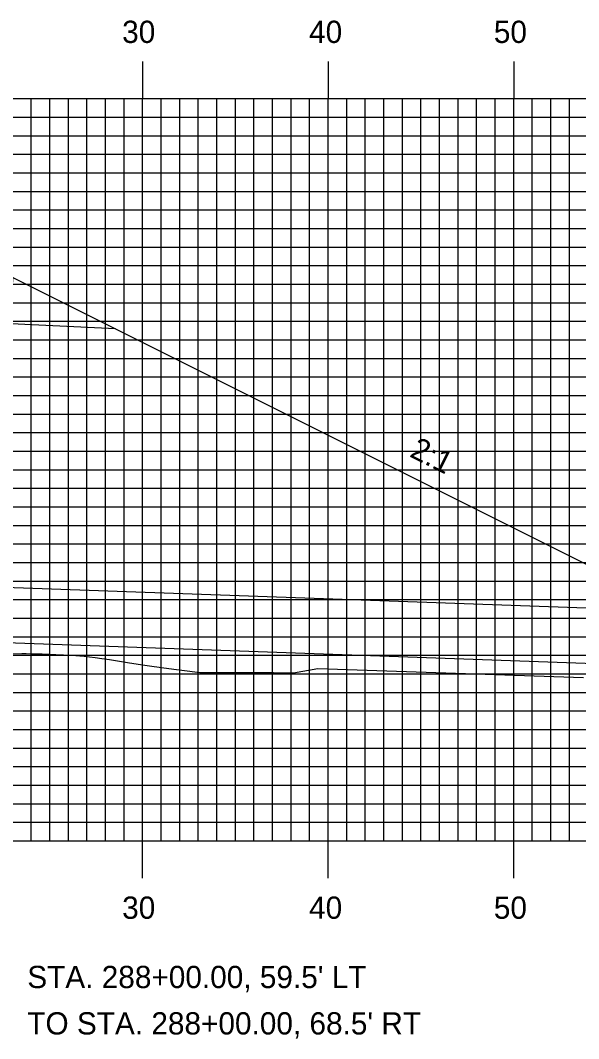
# Model space of a CAD drawing. Extents: x 1812948 to 1813291, y 442591 to 442811.
# Drawn here: x 1813136.9 to 1813167, y 442658 to 442712.9 of the extents above; entities that cross this region are included whole.
import ezdxf

# ---------------------------------------------------------------- set-up
doc = ezdxf.new("R2010")
doc.units = 0
for name, color, linetype in [('ANNOTATION', 7, 'Continuous'), ('D_Drainage_Culvert', 7, 'Continuous'), ('D_Roadway_Centerline', 7, 'Continuous'), ('D_Roadway_SlopeLines', 7, 'Continuous'), ('D_Roadway_SubGrade', 7, 'Continuous'), ('D_Text_Standard', 7, 'Continuous'), ('Default', 7, 'Continuous'), ('H_V ANNOTATION', 7, 'Continuous'), ('MAJOR', 7, 'Continuous'), ('MINOR', 7, 'Continuous'), ('S_Roadway_Centerline', 7, 'Continuous')]:
    doc.layers.add(name, color=color, linetype=linetype)

msp = doc.modelspace()

# ---------------------------------------------------------------- linework, layer by layer
at = {"layer": 'D_Drainage_Culvert'}
msp.add_lwpolyline([(1813053.993, 442682.258), (1813054.1, 442685.256), (1813182.019, 442680.701), (1813181.912, 442677.703)], close=True, dxfattribs=at)
at = {"layer": 'D_Roadway_Centerline'}
msp.add_lwpolyline([(1813053.993, 442682.258), (1813085.247, 442697.885), (1813090.455, 442700.489), (1813093.455, 442700.549), (1813101.455, 442700.709), (1813113.455, 442700.133), (1813125.455, 442699.557), (1813133.455, 442699.173), (1813136.455, 442699.029), (1813141.986, 442696.263), (1813179.261, 442677.626)], dxfattribs=at)
at = {"layer": 'D_Roadway_SlopeLines'}
msp.add_lwpolyline([(1813136.455, 442699.029), (1813179.261, 442677.626)], dxfattribs=at)
at = {"layer": 'D_Roadway_SubGrade'}
msp.add_lwpolyline([(1813125.455, 442698.89), (1813125.455, 442699.307), (1813136.455, 442698.779), (1813136.455, 442699.029), (1813141.986, 442696.263), (1813125.455, 442697.057)], close=True, dxfattribs=at)
at = {"layer": 'Default'}
msp.add_lwpolyline([(1813053.993, 442682.258), (1813054.1, 442685.256), (1813182.019, 442680.701), (1813181.912, 442677.703)], close=True, dxfattribs=at)
at = {"layer": 'MAJOR'}
for p, q in [((1813143.455, 442710.669), (1813143.455, 442708.665)), ((1813153.455, 442710.669), (1813153.455, 442708.665)), ((1813163.455, 442710.669), (1813163.455, 442708.665)), ((1812973.455, 442708.665), (1813253.455, 442708.665)), ((1812973.455, 442708.665), (1813253.455, 442708.665)), ((1813143.455, 442668.665), (1813143.455, 442708.665)), ((1813153.455, 442668.665), (1813153.455, 442708.665)), ((1813163.455, 442668.665), (1813163.455, 442708.665)), ((1812973.455, 442703.665), (1813253.455, 442703.665)), ((1812973.455, 442698.665), (1813253.455, 442698.665)), ((1812973.455, 442693.665), (1813253.455, 442693.665)), ((1812973.455, 442688.665), (1813253.455, 442688.665)), ((1812973.455, 442683.665), (1813253.455, 442683.665)), ((1812973.455, 442678.665), (1813253.455, 442678.665)), ((1812973.455, 442673.665), (1813253.455, 442673.665)), ((1812973.455, 442668.665), (1813253.455, 442668.665)), ((1812973.455, 442668.665), (1813253.455, 442668.665)), ((1813143.455, 442666.661), (1813143.455, 442668.665)), ((1813153.455, 442666.661), (1813153.455, 442668.665)), ((1813163.455, 442666.661), (1813163.455, 442668.665))]:
    msp.add_line(p, q, dxfattribs=at)
at = {"layer": 'MINOR'}
for p, q in [((1813137.455, 442668.665), (1813137.455, 442708.665)), ((1813138.455, 442668.665), (1813138.455, 442708.665)), ((1813139.455, 442668.665), (1813139.455, 442708.665)), ((1813140.455, 442668.665), (1813140.455, 442708.665)), ((1813141.455, 442668.665), (1813141.455, 442708.665)), ((1813142.455, 442668.665), (1813142.455, 442708.665)), ((1813144.455, 442668.665), (1813144.455, 442708.665)), ((1813145.455, 442668.665), (1813145.455, 442708.665)), ((1813146.455, 442668.665), (1813146.455, 442708.665)), ((1813147.455, 442668.665), (1813147.455, 442708.665)), ((1813148.455, 442668.665), (1813148.455, 442708.665)), ((1813149.455, 442668.665), (1813149.455, 442708.665)), ((1813150.455, 442668.665), (1813150.455, 442708.665)), ((1813151.455, 442668.665), (1813151.455, 442708.665)), ((1813152.455, 442668.665), (1813152.455, 442708.665)), ((1813154.455, 442668.665), (1813154.455, 442708.665)), ((1813155.455, 442668.665), (1813155.455, 442708.665)), ((1813156.455, 442668.665), (1813156.455, 442708.665)), ((1813157.455, 442668.665), (1813157.455, 442708.665)), ((1813158.455, 442668.665), (1813158.455, 442708.665)), ((1813159.455, 442668.665), (1813159.455, 442708.665)), ((1813160.455, 442668.665), (1813160.455, 442708.665)), ((1813161.455, 442668.665), (1813161.455, 442708.665)), ((1813162.455, 442668.665), (1813162.455, 442708.665)), ((1813164.455, 442668.665), (1813164.455, 442708.665)), ((1813165.455, 442668.665), (1813165.455, 442708.665)), ((1813166.455, 442668.665), (1813166.455, 442708.665)), ((1812973.455, 442707.665), (1813253.455, 442707.665)), ((1812973.455, 442706.665), (1813253.455, 442706.665)), ((1812973.455, 442705.665), (1813253.455, 442705.665)), ((1812973.455, 442704.665), (1813253.455, 442704.665)), ((1812973.455, 442702.665), (1813253.455, 442702.665)), ((1812973.455, 442701.665), (1813253.455, 442701.665)), ((1812973.455, 442700.665), (1813253.455, 442700.665)), ((1812973.455, 442699.665), (1813253.455, 442699.665)), ((1812973.455, 442697.665), (1813253.455, 442697.665)), ((1812973.455, 442696.665), (1813253.455, 442696.665)), ((1812973.455, 442695.665), (1813253.455, 442695.665)), ((1812973.455, 442694.665), (1813253.455, 442694.665)), ((1812973.455, 442692.665), (1813253.455, 442692.665)), ((1812973.455, 442691.665), (1813253.455, 442691.665)), ((1812973.455, 442690.665), (1813253.455, 442690.665)), ((1812973.455, 442689.665), (1813253.455, 442689.665)), ((1812973.455, 442687.665), (1813253.455, 442687.665)), ((1812973.455, 442686.665), (1813253.455, 442686.665)), ((1812973.455, 442685.665), (1813253.455, 442685.665)), ((1812973.455, 442684.665), (1813253.455, 442684.665)), ((1812973.455, 442682.665), (1813253.455, 442682.665)), ((1812973.455, 442681.665), (1813253.455, 442681.665)), ((1812973.455, 442680.665), (1813253.455, 442680.665)), ((1812973.455, 442679.665), (1813253.455, 442679.665)), ((1812973.455, 442677.665), (1813253.455, 442677.665)), ((1812973.455, 442676.665), (1813253.455, 442676.665)), ((1812973.455, 442675.665), (1813253.455, 442675.665)), ((1812973.455, 442674.665), (1813253.455, 442674.665)), ((1812973.455, 442672.665), (1813253.455, 442672.665)), ((1812973.455, 442671.665), (1813253.455, 442671.665)), ((1812973.455, 442670.665), (1813253.455, 442670.665)), ((1812973.455, 442669.665), (1813253.455, 442669.665))]:
    msp.add_line(p, q, dxfattribs=at)
at = {"layer": 'S_Roadway_Centerline'}
msp.add_lwpolyline([(1813127.287, 442678.726), (1813136.95, 442678.762), (1813137.175, 442678.758), (1813137.431, 442678.752), (1813137.721, 442678.746), (1813138.042, 442678.737), (1813138.396, 442678.726), (1813138.78, 442678.712), (1813139.19, 442678.694), (1813139.622, 442678.671), (1813140.068, 442678.643), (1813140.307, 442678.622), (1813140.584, 442678.59), (1813140.901, 442678.549), (1813141.262, 442678.497), (1813141.671, 442678.435), (1813142.644, 442678.283), (1813143.209, 442678.195), (1813143.821, 442678.101), (1813144.469, 442678.006), (1813145.133, 442677.915), (1813145.859, 442677.821), (1813146.53, 442677.737), (1813146.842, 442677.736), (1813147.972, 442677.733), (1813148.845, 442677.732), (1813149.528, 442677.732), (1813150.07, 442677.731), (1813150.506, 442677.73), (1813150.859, 442677.728), (1813151.149, 442677.725), (1813151.389, 442677.721), (1813151.589, 442677.715), (1813152.892, 442677.95), (1813167.219, 442677.471)], dxfattribs=at)

# ---------------------------------------------------------------- texts
at = {"layer": 'ANNOTATION'}
msp.add_text('2:1', height=1.2, rotation=333.4349, dxfattribs=at).set_placement((1813157.792, 442689.396))
at = {"layer": 'D_Text_Standard'}
for s, p in [("STA. 288+00.00, 59.5' LT", (1813137.238, 442660.73)), ("TO STA. 288+00.00, 68.5' RT", (1813137.238, 442658.23))]:
    msp.add_text(s, height=1.2, dxfattribs=at).set_placement(p)
at = {"layer": 'H_V ANNOTATION'}
for s, p in [('30', (1813142.352, 442711.665)), ('40', (1813152.427, 442711.665)), ('50', (1813162.384, 442711.665)), ('30', (1813142.352, 442664.465)), ('40', (1813152.427, 442664.465)), ('50', (1813162.384, 442664.465))]:
    msp.add_text(s, height=1.2, dxfattribs=at).set_placement(p)

doc.saveas('drawing.dxf')
